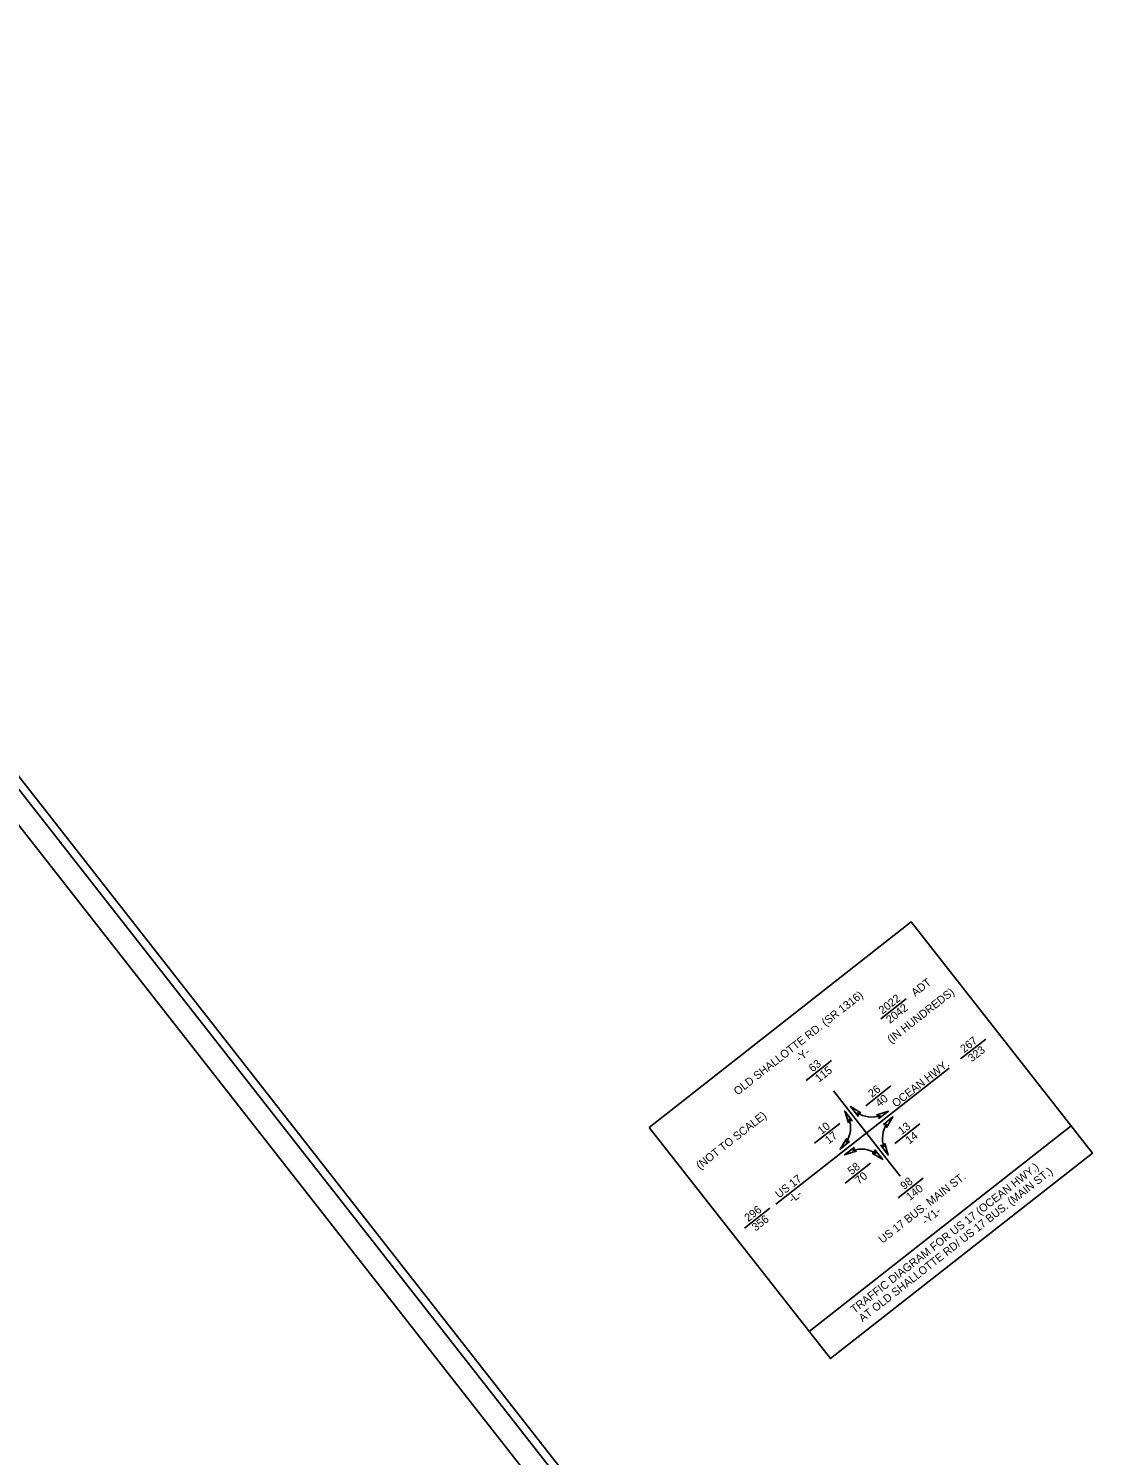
# Model space of a CAD drawing. Extents: x 2176242 to 2178501, y 76147 to 78096.
# Drawn here: x 2177903 to 2178501, y 77249 to 78051 of the extents above; entities that cross this region are included whole.
import ezdxf

# ---------------------------------------------------------------- set-up
doc = ezdxf.new("R2010")
doc.units = 0
for name, color, linetype in [('CTL Primary Horizontal and Vertical CELL', 7, 'Continuous'), ('CTL Primary Horizontal and Vertical Cogo Elevation', 7, 'Continuous'), ('CTL Primary Horizontal CELL', 7, 'Continuous'), ('CTL Primary Horizontal Cogo Number', 7, 'Continuous'), ('Default', 7, 'Continuous'), ('Exist Other Culture Sign Cogo Point CELL', 7, 'Continuous'), ('Exist Utilities Other Pole CELL', 7, 'Continuous')]:
    doc.layers.add(name, color=color, linetype=linetype)

msp = doc.modelspace()

# ---------------------------------------------------------------- linework, layer by layer
at = {"layer": 'CTL Primary Horizontal and Vertical CELL'}
msp.add_lwpolyline([(2176602.37, 76823.57), (2177301.95, 77811.08), (2177301.95, 77811.08), (2177306.48, 77814.63), (2177363.51, 77741.87), (2177469.29, 77824.79), (2177519.32, 77760.95), (2177676.76, 77884.36), (2178217.46, 77194.57), (2177036.91, 76269.2)], close=True, dxfattribs=at)
at = {"layer": 'CTL Primary Horizontal and Vertical Cogo Elevation'}
for p, q in [((2178382.26, 77494.41), (2178396.45, 77505.54)), ((2178427.05, 77471.78), (2178441.24, 77482.91)), ((2178323.13, 77390.12), (2178420.6, 77466.56)), ((2178340.22, 77459.76), (2178354.41, 77470.88)), ((2178355.52, 77453.85), (2178393.14, 77405.88)), ((2178373.7, 77445.47), (2178387.89, 77456.6)), ((2178341.83, 77318.62), (2178489.22, 77434.21)), ((2178344.94, 77424.37), (2178359.13, 77435.5)), ((2178390.02, 77424.2), (2178404.21, 77435.33)), ((2178362.18, 77401.99), (2178376.37, 77413.12)), ((2178391.85, 77393.64), (2178406.04, 77404.77)), ((2178305.53, 77376.72), (2178319.72, 77387.85))]:
    msp.add_line(p, q, dxfattribs=at)
msp.add_lwpolyline([(2178251.9, 77433.28), (2178399.29, 77548.88), (2178501.24, 77418.87), (2178353.86, 77303.28)], close=True, dxfattribs=at)
for centre, start, end in [((2178349.85, 77433.06), 327.54154, 19.12827), ((2178377.07, 77454.4), 237.08366, 288.67039), ((2178398.42, 77427.18), 147.54154, 199.12827), ((2178371.2, 77405.83), 57.08366, 108.67039)]:
    msp.add_arc(centre, 15.29, start, end, dxfattribs=at)
at = {"layer": 'CTL Primary Horizontal CELL'}
msp.add_lwpolyline([(2177577.97, 78030.67), (2176266.38, 77002.59), (2176917.29, 76172.19), (2178228.87, 77200.28)], close=True, dxfattribs=at)
at = {"layer": 'CTL Primary Horizontal Cogo Number'}
msp.add_lwpolyline([(2177567.66, 78051.12), (2176242.3, 77012.24), (2176920.9, 76146.5), (2178246.26, 77185.38)], close=True, dxfattribs=at)
at = {"layer": 'Default'}
for points in [[(2178363.92, 77435.95), (2178361.88, 77442.49), (2178366.04, 77436.99), (2178364.58, 77437.22)], [(2178370.9, 77441.43), (2178365.04, 77444.97), (2178369.39, 77439.62), (2178369.52, 77441.09)], [(2178381.04, 77438.24), (2178386.5, 77442.37), (2178379.92, 77440.32), (2178381.24, 77439.65)], [(2178383.67, 77434.89), (2178388.98, 77439.21), (2178385.42, 77433.3), (2178385.09, 77434.74)], [(2178364.6, 77425.35), (2178359.29, 77421.03), (2178362.85, 77426.93), (2178363.19, 77425.49)], [(2178367.23, 77422), (2178361.77, 77417.86), (2178368.35, 77419.91), (2178367.03, 77420.58)], [(2178377.37, 77418.81), (2178383.23, 77415.27), (2178378.89, 77420.62), (2178378.75, 77419.15)], [(2178384.35, 77424.28), (2178386.39, 77417.74), (2178382.23, 77423.24), (2178383.69, 77423.02)]]:
    msp.add_lwpolyline(points, close=True, dxfattribs=at)
at = {"layer": 'Exist Other Culture Sign Cogo Point CELL'}
msp.add_lwpolyline([(2177569.7, 78020.95), (2176389.16, 77095.58), (2177036.91, 76269.2), (2178217.46, 77194.57)], close=True, dxfattribs=at)

# ---------------------------------------------------------------- texts
at = {"layer": 'Exist Utilities Other Pole CELL'}
for s, p in [('ADT', (2178401.5, 77506.62)), ('OLD SHALLOTTE RD. (SR 1316)', (2178301.62, 77451.15)), ('2022', (2178383.14, 77496.73)), ('(IN HUNDREDS)', (2178387.95, 77480.29)), ('2042', (2178387.3, 77491.42)), ('267', (2178429.05, 77474.99)), ('-Y-', (2178336.46, 77469.9)), ('323', (2178433.38, 77469.8)), ('63', (2178343.78, 77464.18)), ('115', (2178347.38, 77458.43)), ('OCEAN HWY.', (2178390.65, 77444.35)), ('26', (2178377.19, 77449.85)), ('40', (2178381.35, 77444.53)), ('(NOT TO SCALE)', (2178280.44, 77409.44)), ('10', (2178348.85, 77429.07)), ('13', (2178394.01, 77428.96)), ('17', (2178352.93, 77423.7)), ('14', (2178398.19, 77423.67)), ('58', (2178365.67, 77406.36)), ('TRAFFIC DIAGRAM FOR US 17 (OCEAN HWY.)', (2178367.34, 77328.54)), ('AT OLD SHALLOTTE RD/ US 17 BUS. (MAIN ST.)', (2178371.95, 77323.58)), ('US 17', (2178324.94, 77393.26)), ('70', (2178369.83, 77401.05)), ('US 17 BUS. MAIN ST.', (2178383.09, 77367.82)), ('98', (2178395.34, 77398.01)), ('-L-', (2178332.42, 77390.55)), ('140', (2178398.52, 77391.93)), ('296', (2178307.63, 77380)), ('-Y1-', (2178407.44, 77378.33)), ('356', (2178311.79, 77374.69))]:
    msp.add_text(s, height=4.5, rotation=38.10599, dxfattribs=at).set_placement(p)

doc.saveas('drawing.dxf')
